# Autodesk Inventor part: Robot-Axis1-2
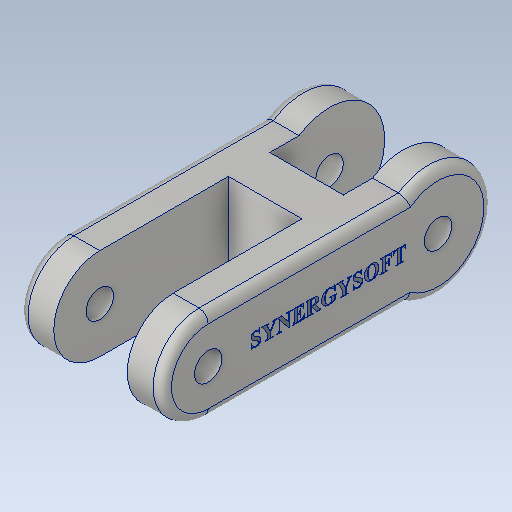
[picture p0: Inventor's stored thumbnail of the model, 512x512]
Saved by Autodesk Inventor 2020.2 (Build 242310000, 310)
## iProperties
Created: 2018-07
Part Number: Robot-Axis1-2
Material: Aluminum 6061
Description: 123456
Document SubType Name: Modeling
Designer: Power User
Mass: 7772.34 g
Surface Area: 2206.67 cm^2
Volume: 2878.64 cm^3
Density: 2.7 g/cm^3
Appearance: Aluminum - Flat
Title: GEAR
Author: Power User
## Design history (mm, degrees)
sketch "Sketch6"
  geometry: L1 (0, 250)-(0, 0); L2 (-50, 250)-(-50, 0); L3 (50, 0)-(50, 250); C1 r 15 at (0, 0); C2 r 60 at (0, 0); C3 r 15 at (0, 250); A1 r 50 centre (0, 250) between (50, 250) and (-50, 250); A2 r 50 centre (0, 0) between (-50, 0) and (50, 0); 2 further points
  constraints: 8 end point, 5 centre point, 4 point on circle, 4 tangent, 3 coincident, 1 midpoint, 1 parallel, 1 vertical
  dimensions: "d44" = 30 diameter of C1; "d45" = 120 diameter of C2; "d46" = 100 diameter of A2; "d47" = 250 distance of L1.start L1.end; "d48" = 30 diameter of C3
extrude "Extrusion5" new body sketch "Sketch6" stored distance "d49" = 156; taper "d50" = 0 deg
sketch "Sketch7"
  geometry: L1 (40, 300)-(-40, 300); L2 (-40, 300)-(-40, 110); L3 (-40, 110)-(40, 110); L4 (40, 110)-(40, 300); L5 (40, 65)-(-40, 65); L6 (-40, 65)-(-40, -60); L7 (-40, -60)-(40, -60); L8 (40, -60)-(40, 65); L9 (78, 265)-(-78, 265) reference; L10 (-78, 265)-(-78, 300) reference; L11 (-78, 300)-(78, 300) reference; L12 (78, 300)-(78, 265) reference; L13 (-78, -15)-(78, -15) reference; L14 (78, -15)-(78, -60) reference; L15 (78, -60)-(-78, -60) reference; L16 (-78, -60)-(-78, -15) reference; L17 (78, 15)-(-78, 15) reference; L18 (-78, 15)-(-78, 235) reference; L19 (-78, 235)-(78, 235) reference; L20 (78, 235)-(78, 15) reference; 2 further points
  constraints: 16 end point, 4 collinear, 4 parallel, 2 horizontal, 2 perpendicular, 1 midpoint, 1 vertical alignment
  dimensions: "d51" = 45 distance between parallel lines of L5 L3; "d52" = 125 distance of L5.end L6.end; "d53" = 80 distance of L1.start L1.end
extrude "Extrusion6" cut sketch "Sketch7" extent not by distance; stored distance "d54" = 156; taper "d55" = 0 deg
fillet "Fillet2" dims "d56" = 10
sketch "Sketch8"
  geometry: L1 (-208.793, 20.97)-(-30, 20.97); L2 (-30, 20.97)-(-30, -20.97); L3 (-30, -20.97)-(-208.793, -20.97); L4 (-208.793, -20.97)-(-208.793, 20.97); 2 further points
  constraints: 1 horizontal, 1 horizontal alignment, 1 midpoint, 2 other
  dimensions: "d57" = 30 distance from line of point (0, 0) L2
emboss "Emboss1" sketch "Sketch8" dims "d44" = 30, "d45" = 120, "d46" = 100, "d47" = 250, "d48" = 30, "d58" = 0.5, "d59" = 0
body "Solid2"
node "Project Cut Edges2"
